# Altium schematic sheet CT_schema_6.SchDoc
size 427 x 414 mm
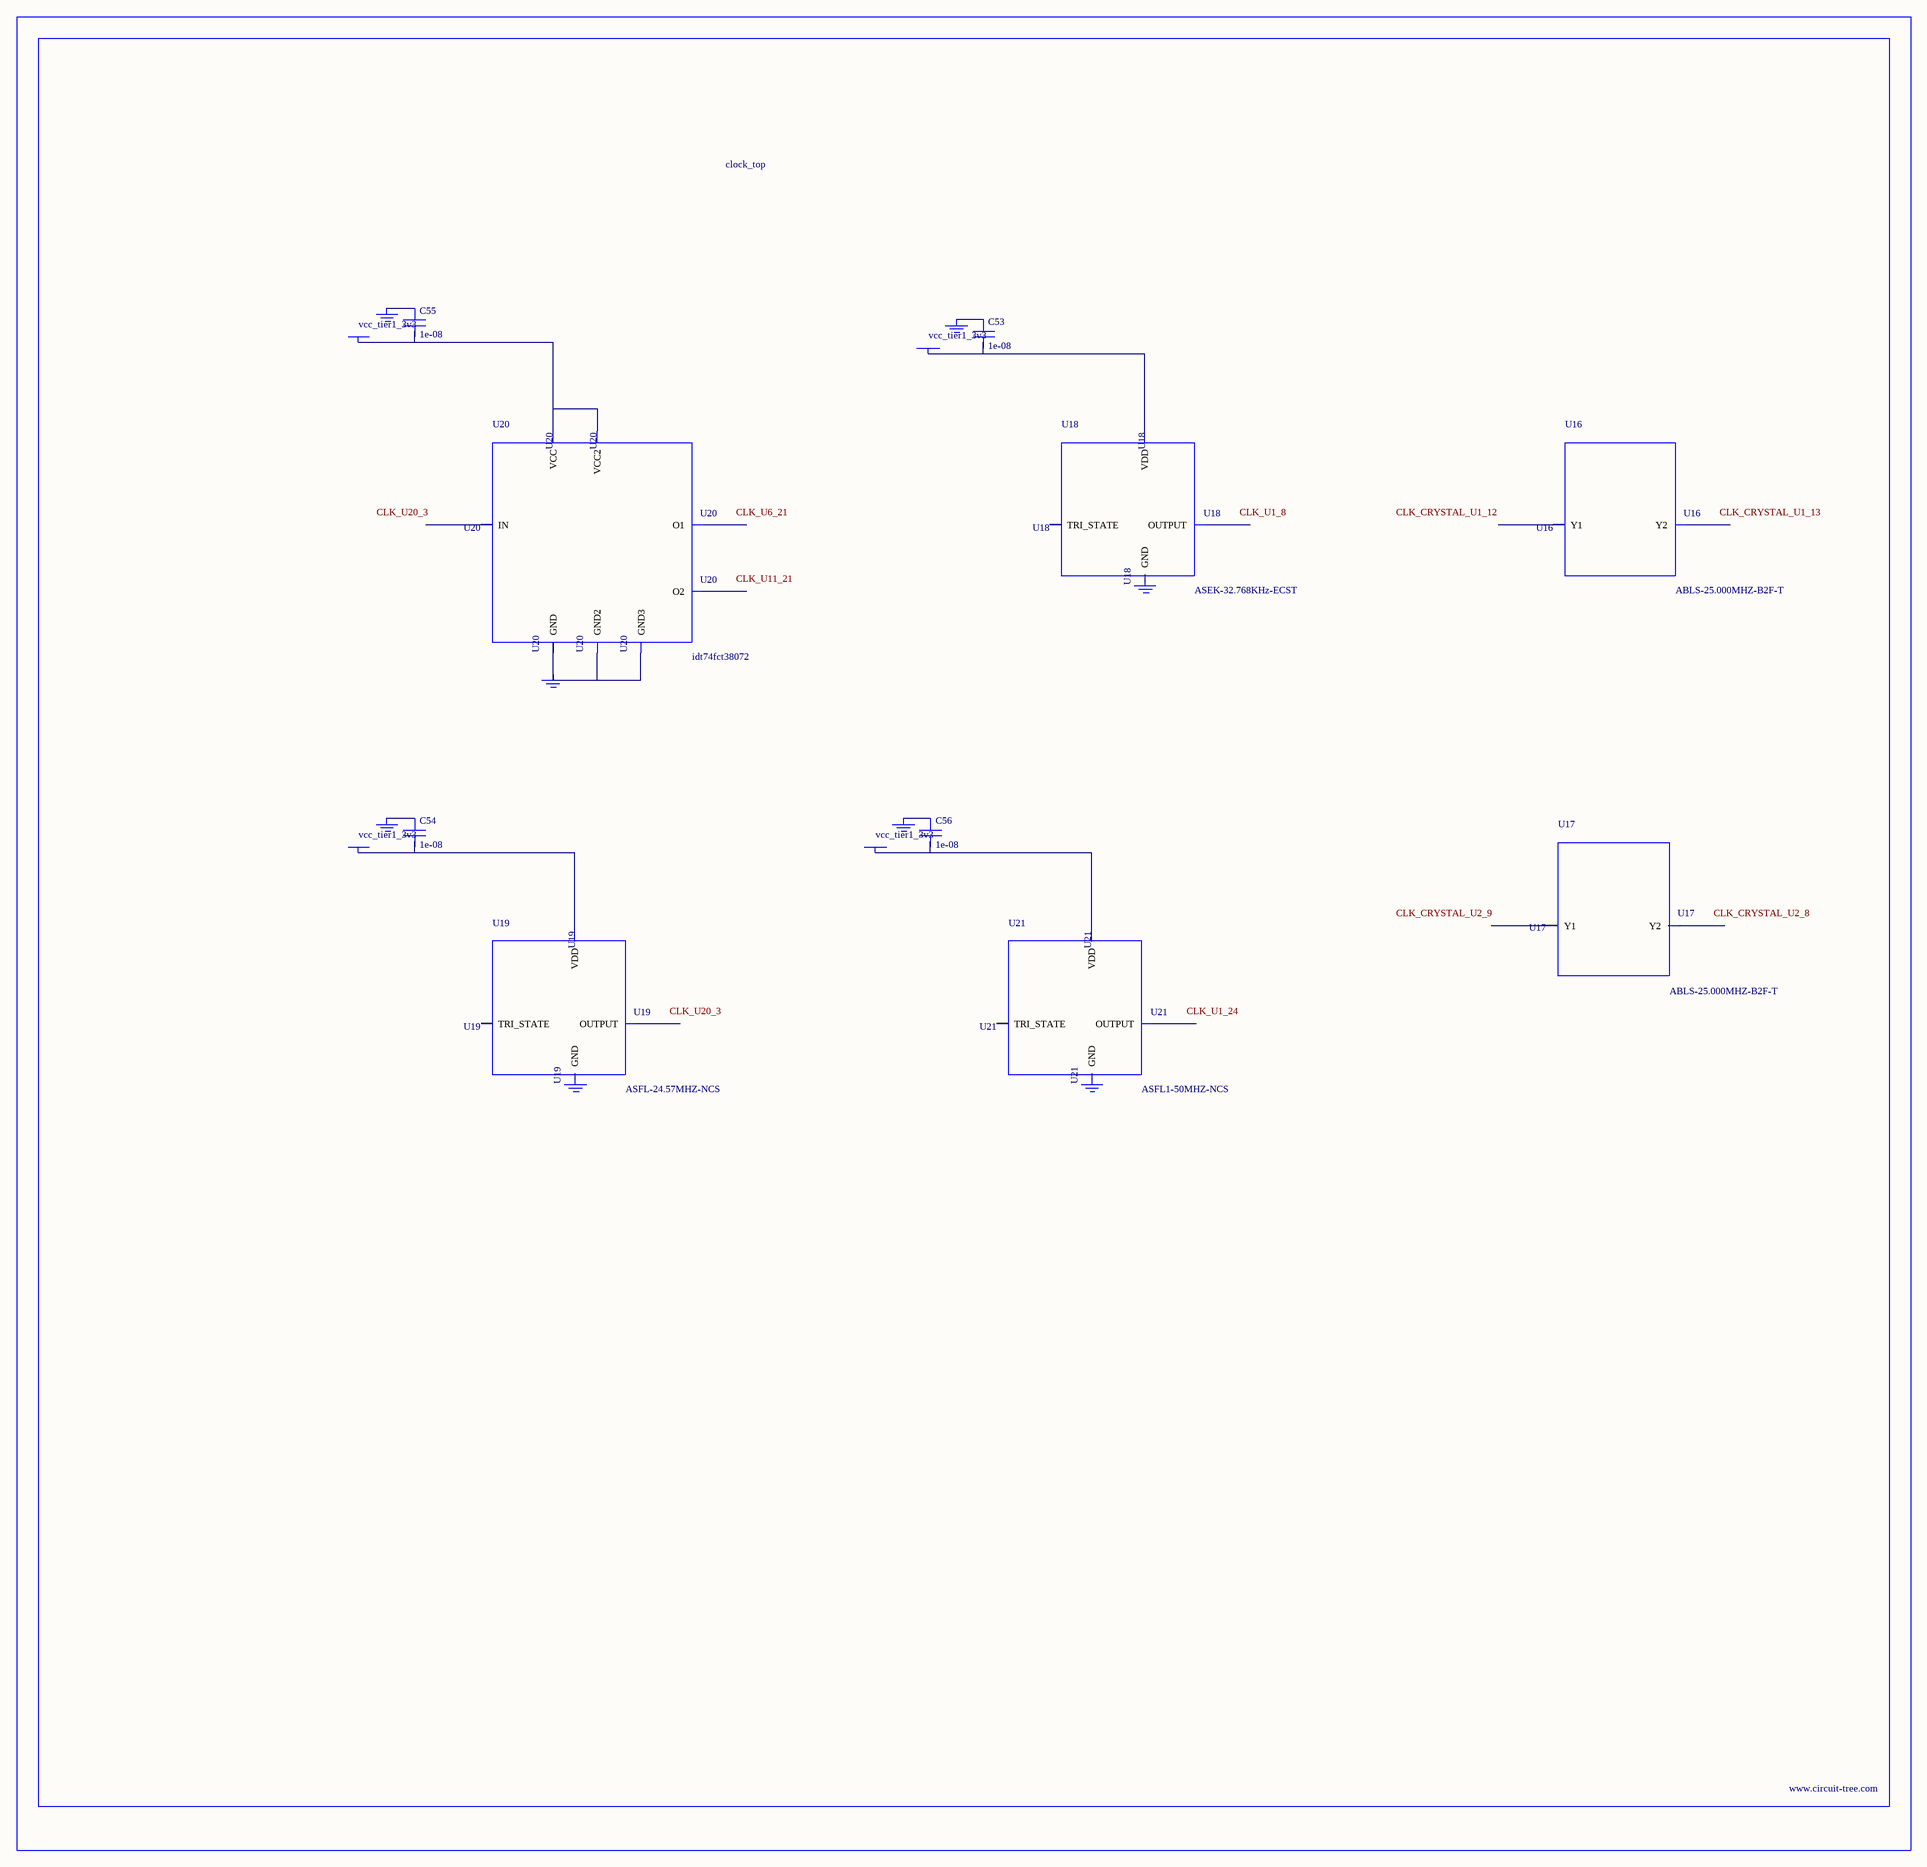
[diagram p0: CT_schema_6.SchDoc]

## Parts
BORDER5  (no value)
C53  1e-08  [C0402]
C54  1e-08  [C0402]
C55  1e-08  [C0402]
C56  1e-08  [C0402]
GND_INSTANCE_5_0  (no value)
GND_INSTANCE_5_1  (no value)
GND_INSTANCE_5_2  (no value)
GND_INSTANCE_5_3  (no value)
GND_INSTANCE_5_4  (no value)
GND_INSTANCE_5_5  (no value)
GND_INSTANCE_5_6  (no value)
GND_INSTANCE_5_7  (no value)
POWER_INSTANCE_5_0  vcc_tier1_3v3
POWER_INSTANCE_5_1  vcc_tier1_3v3
POWER_INSTANCE_5_2  vcc_tier1_3v3
POWER_INSTANCE_5_3  vcc_tier1_3v3
U16  ABLS-25.000MHZ-B2F-T  [ABLS-25.000MHZ-B2F-T]
U17  ABLS-25.000MHZ-B2F-T  [ABLS-25.000MHZ-B2F-T]
U18  ASEK-32.768KHz-ECST  [ASEK]
U19  ASFL-24.57MHZ-NCS  [ASFL1]
U20  idt74fct38072  [IDT74FCT38072]
U21  ASFL1-50MHZ-NCS  [ASFL1]

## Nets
NetC53_1: C53.1 GND_INSTANCE_5_0.0(GND)
NetC53_2: C53.2 POWER_INSTANCE_5_0.0(PWR) U18.4(VDD)
NetC54_1: C54.1 GND_INSTANCE_5_2.0(GND)
NetC54_2: C54.2 POWER_INSTANCE_5_1.0(PWR) U19.4(VDD)
NetC55_1: C55.1 GND_INSTANCE_5_4.0(GND)
NetC55_2: C55.2 POWER_INSTANCE_5_2.0(PWR) U20.1(VCC) U20.2(VCC2)
NetC56_1: C56.1 GND_INSTANCE_5_6.0(GND)
NetC56_2: C56.2 POWER_INSTANCE_5_3.0(PWR) U21.4(VDD)
NetGND_INSTANCE_5_5_0: GND_INSTANCE_5_5.0(GND) U20.4(GND) U20.5(GND2) U20.8(GND3)

Not connected (* = marked no-connect by the designer): GND_INSTANCE_5_1 0(GND); GND_INSTANCE_5_3 0(GND); GND_INSTANCE_5_7 0(GND); U16 1(Y1) 2(Y2); U17 1(Y1) 2(Y2); U18 1(TRI_STATE) 2(GND) 3(OUTPUT); U19 1(TRI_STATE) 2(GND) 3(OUTPUT); U20 3(IN) 6(O2) 7(O1); U21 1(TRI_STATE) 2(GND) 3(OUTPUT)

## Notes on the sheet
- Labels drawn without touching a wire or pin: CLK_CRYSTAL_U1_12, CLK_CRYSTAL_U1_13, CLK_CRYSTAL_U2_8, CLK_CRYSTAL_U2_9, CLK_U1_8, CLK_U1_24, CLK_U6_21, CLK_U11_21, CLK_U20_3

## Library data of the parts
BORDER5 = BORDER_PAGE5
C53-C56 = C0402C103K3RAC
GND_INSTANCE_5_0-GND_INSTANCE_5_7 = GND
POWER_INSTANCE_5_0-POWER_INSTANCE_5_3 = PWR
